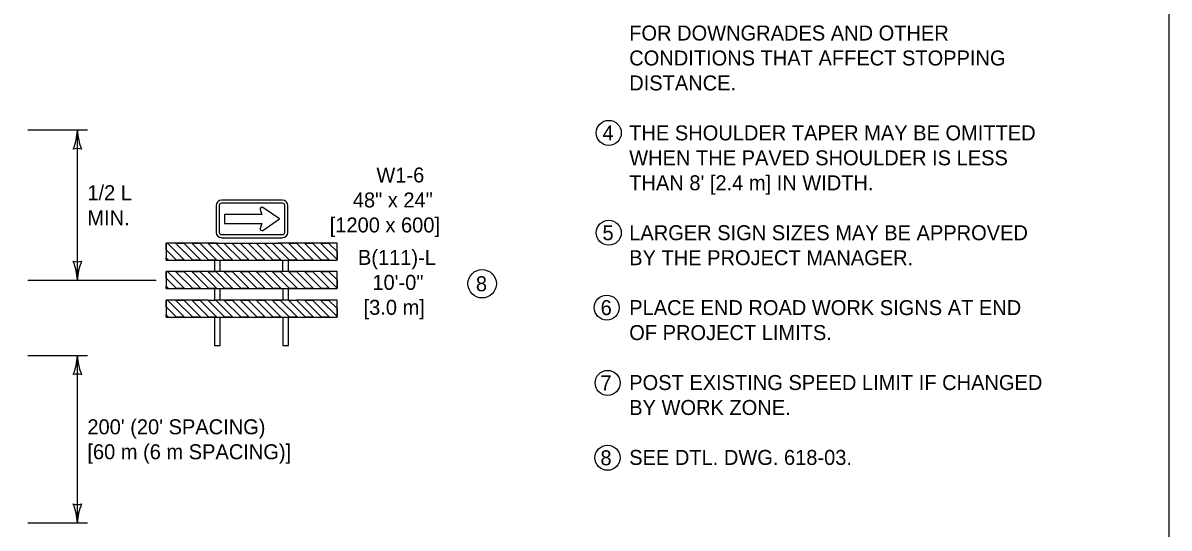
# Model space of a CAD drawing. Extents: x 49991.4 to 50021, y 49987.6 to 50011.4.
# Drawn here: x 50004.026 to 50008.615, y 50006.247 to 50008.271 of the extents above; entities that cross this region are included whole.
import ezdxf

# ---------------------------------------------------------------- set-up
doc = ezdxf.new("R2010")
doc.units = 0
for name, color, linetype in [('Level 1', 7, 'Continuous'), ('Level 2', 7, 'Continuous'), ('Level 3', 7, 'Continuous')]:
    doc.layers.add(name, color=color, linetype=linetype)

msp = doc.modelspace()

# ---------------------------------------------------------------- linework, layer by layer
at = {"layer": 'Level 1'}
for p, q in [((50004.7996, 50007.5398), (50004.7996, 50007.4315)), ((50004.812, 50007.5398), (50004.812, 50007.4315)), ((50005.0657, 50007.5607), (50004.8206, 50007.5607)), ((50005.0657, 50007.5483), (50004.8206, 50007.5483)), ((50005.0742, 50007.4315), (50005.0742, 50007.5398)), ((50005.0866, 50007.4315), (50005.0866, 50007.5398)), ((50004.9718, 50007.5039), (50004.8336, 50007.5039)), ((50004.8336, 50007.5039), (50004.8336, 50007.4674)), ((50004.982, 50007.5039), (50004.9718, 50007.5039)), ((50004.9756, 50007.5234), (50004.982, 50007.5039)), ((50005.0526, 50007.4856), (50004.9862, 50007.5313)), ((50004.8336, 50007.4674), (50004.982, 50007.4674)), ((50004.982, 50007.4674), (50004.9756, 50007.4478)), ((50004.9862, 50007.4399), (50005.0526, 50007.4856)), ((50004.8206, 50007.4229), (50005.0657, 50007.4229)), ((50004.8206, 50007.4105), (50005.0657, 50007.4105)), ((50004.6413, 50007.3203), (50004.5996, 50007.3621)), ((50004.6413, 50007.3203), (50004.5996, 50007.3621)), ((50004.6735, 50007.3203), (50004.6051, 50007.3887)), ((50004.6051, 50007.3887), (50004.6735, 50007.3203)), ((50004.7058, 50007.3203), (50004.6374, 50007.3887)), ((50004.7058, 50007.3203), (50004.6374, 50007.3887)), ((50004.7381, 50007.3203), (50004.6697, 50007.3887)), ((50004.6697, 50007.3887), (50004.7381, 50007.3203)), ((50004.7703, 50007.3203), (50004.7019, 50007.3887)), ((50004.7703, 50007.3203), (50004.7019, 50007.3887)), ((50004.8025, 50007.3203), (50004.7341, 50007.3887)), ((50004.7341, 50007.3887), (50004.8025, 50007.3203)), ((50004.8348, 50007.3203), (50004.7664, 50007.3887)), ((50004.867, 50007.3203), (50004.7986, 50007.3887)), ((50004.7986, 50007.3887), (50004.8385, 50007.3887)), ((50004.819, 50007.3887), (50005.0641, 50007.3887)), ((50004.8992, 50007.3203), (50004.8308, 50007.3887)), ((50004.9314, 50007.3203), (50004.863, 50007.3887)), ((50004.9636, 50007.3203), (50004.8952, 50007.3887)), ((50004.9958, 50007.3203), (50004.9274, 50007.3887)), ((50005.028, 50007.3203), (50004.9596, 50007.3887)), ((50005.0602, 50007.3203), (50004.9918, 50007.3887)), ((50005.0927, 50007.3203), (50005.0243, 50007.3887)), ((50005.0784, 50007.3887), (50005.047, 50007.3887)), ((50005.1249, 50007.3203), (50005.0565, 50007.3887)), ((50005.1572, 50007.3203), (50005.0888, 50007.3887)), ((50005.1572, 50007.3203), (50005.0888, 50007.3887)), ((50005.1894, 50007.3203), (50005.121, 50007.3887)), ((50005.121, 50007.3887), (50005.1894, 50007.3203)), ((50005.2217, 50007.3203), (50005.1533, 50007.3887)), ((50005.2217, 50007.3203), (50005.1533, 50007.3887)), ((50005.2539, 50007.3203), (50005.1855, 50007.3887)), ((50005.1855, 50007.3887), (50005.2539, 50007.3203)), ((50005.2836, 50007.3229), (50005.2177, 50007.3887)), ((50005.2836, 50007.3229), (50005.2177, 50007.3887)), ((50005.2836, 50007.3551), (50005.25, 50007.3887)), ((50005.25, 50007.3887), (50005.2836, 50007.3551)), ((50004.6091, 50007.3203), (50004.5996, 50007.3298)), ((50004.5996, 50007.3298), (50004.6091, 50007.3203)), ((50004.8162, 50007.2748), (50004.8162, 50007.3203)), ((50005.067, 50007.2748), (50005.067, 50007.3203)), ((50004.6735, 50007.2064), (50004.6051, 50007.2748)), ((50004.6051, 50007.2748), (50004.6735, 50007.2064)), ((50004.7058, 50007.2064), (50004.6374, 50007.2748)), ((50004.7058, 50007.2064), (50004.6374, 50007.2748)), ((50004.7381, 50007.2064), (50004.6697, 50007.2748)), ((50004.6697, 50007.2748), (50004.7381, 50007.2064)), ((50004.7703, 50007.2064), (50004.7019, 50007.2748)), ((50004.7703, 50007.2064), (50004.7019, 50007.2748)), ((50004.8025, 50007.2064), (50004.7341, 50007.2748)), ((50004.7341, 50007.2748), (50004.8025, 50007.2064)), ((50004.8048, 50007.2364), (50004.7664, 50007.2748)), ((50004.8048, 50007.2686), (50004.7986, 50007.2748)), ((50004.867, 50007.2064), (50004.8048, 50007.2686)), ((50004.8993, 50007.2064), (50004.8309, 50007.2748)), ((50004.9315, 50007.2064), (50004.8631, 50007.2748)), ((50004.9637, 50007.2064), (50004.8953, 50007.2748)), ((50004.996, 50007.2064), (50004.9276, 50007.2748)), ((50005.0282, 50007.2064), (50004.9598, 50007.2748)), ((50005.0605, 50007.2064), (50004.9921, 50007.2748)), ((50005.0927, 50007.2064), (50005.0243, 50007.2748)), ((50005.1249, 50007.2064), (50005.0565, 50007.2748)), ((50005.1572, 50007.2064), (50005.0888, 50007.2748)), ((50005.1572, 50007.2064), (50005.0888, 50007.2748)), ((50005.1894, 50007.2064), (50005.121, 50007.2748)), ((50005.121, 50007.2748), (50005.1894, 50007.2064)), ((50005.2217, 50007.2064), (50005.1533, 50007.2748)), ((50005.2217, 50007.2064), (50005.1533, 50007.2748)), ((50005.2539, 50007.2064), (50005.1855, 50007.2748)), ((50005.1855, 50007.2748), (50005.2539, 50007.2064)), ((50005.2836, 50007.2089), (50005.2177, 50007.2748)), ((50005.2836, 50007.2089), (50005.2177, 50007.2748)), ((50005.2836, 50007.2411), (50005.25, 50007.2748)), ((50005.25, 50007.2748), (50005.2836, 50007.2411)), ((50004.6413, 50007.2064), (50004.5996, 50007.2481)), ((50004.6413, 50007.2064), (50004.5996, 50007.2481)), ((50004.8348, 50007.2064), (50004.8048, 50007.2364)), ((50004.6091, 50007.2064), (50004.5996, 50007.2159)), ((50004.5996, 50007.2159), (50004.6091, 50007.2064)), ((50004.6413, 50007.0924), (50004.5996, 50007.1341)), ((50004.6413, 50007.0924), (50004.5996, 50007.1341)), ((50004.6735, 50007.0924), (50004.6051, 50007.1608)), ((50004.6051, 50007.1608), (50004.6735, 50007.0924)), ((50004.7058, 50007.0924), (50004.6374, 50007.1608)), ((50004.7058, 50007.0924), (50004.6374, 50007.1608)), ((50004.7381, 50007.0924), (50004.6697, 50007.1608)), ((50004.6697, 50007.1608), (50004.7381, 50007.0924)), ((50004.7703, 50007.0924), (50004.7019, 50007.1608)), ((50004.7703, 50007.0924), (50004.7019, 50007.1608)), ((50004.8025, 50007.0924), (50004.7341, 50007.1608)), ((50004.7341, 50007.1608), (50004.8025, 50007.0924)), ((50004.8348, 50007.0924), (50004.7664, 50007.1608)), ((50004.8348, 50007.0924), (50004.7664, 50007.1608)), ((50004.867, 50007.0924), (50004.7986, 50007.1608)), ((50004.7986, 50007.1608), (50004.867, 50007.0924)), ((50004.8993, 50007.0924), (50004.8309, 50007.1608)), ((50004.8993, 50007.0924), (50004.8309, 50007.1608)), ((50004.9315, 50007.0924), (50004.8631, 50007.1608)), ((50004.8631, 50007.1608), (50004.9315, 50007.0924)), ((50004.9637, 50007.0924), (50004.8953, 50007.1608)), ((50004.9637, 50007.0924), (50004.8953, 50007.1608)), ((50004.996, 50007.0924), (50004.9276, 50007.1608)), ((50004.9276, 50007.1608), (50004.996, 50007.0924)), ((50005.0282, 50007.0924), (50004.9598, 50007.1608)), ((50005.0282, 50007.0924), (50004.9598, 50007.1608)), ((50005.0605, 50007.0924), (50004.9921, 50007.1608)), ((50004.9921, 50007.1608), (50005.0605, 50007.0924)), ((50005.0927, 50007.0924), (50005.0243, 50007.1608)), ((50005.0927, 50007.0924), (50005.0243, 50007.1608)), ((50005.1249, 50007.0924), (50005.0565, 50007.1608)), ((50005.0565, 50007.1608), (50005.1249, 50007.0924)), ((50005.1572, 50007.0924), (50005.0888, 50007.1608)), ((50005.1572, 50007.0924), (50005.0888, 50007.1608)), ((50005.1894, 50007.0924), (50005.121, 50007.1608)), ((50005.121, 50007.1608), (50005.1894, 50007.0924)), ((50005.2217, 50007.0924), (50005.1533, 50007.1608)), ((50005.2217, 50007.0924), (50005.1533, 50007.1608)), ((50005.2539, 50007.0924), (50005.1855, 50007.1608)), ((50005.1855, 50007.1608), (50005.2539, 50007.0924)), ((50005.2836, 50007.0949), (50005.2177, 50007.1608)), ((50005.2836, 50007.0949), (50005.2177, 50007.1608)), ((50005.2836, 50007.1272), (50005.25, 50007.1608)), ((50005.25, 50007.1608), (50005.2836, 50007.1272)), ((50004.6091, 50007.0924), (50004.5996, 50007.1019)), ((50004.5996, 50007.1019), (50004.6091, 50007.0924))]:
    msp.add_line(p, q, dxfattribs=at)
msp.add_lwpolyline([(50008.6146, 50011.2628), (50000.3356, 50011.2628), (50000.3356, 50000.0624), (50008.6146, 50000.0624)], close=True, dxfattribs=at)
for points in [[(50004.8048, 50007.3887), (50004.5996, 50007.3887), (50004.5996, 50007.3203), (50004.8048, 50007.3203)], [(50004.5996, 50007.3621), (50004.5996, 50007.3887), (50004.6051, 50007.3887)], [(50004.6374, 50007.3887), (50004.6697, 50007.3887)], [(50004.7019, 50007.3887), (50004.7341, 50007.3887)], [(50004.867, 50007.3203), (50004.8348, 50007.3203), (50004.7664, 50007.3887), (50004.7986, 50007.3887), (50004.867, 50007.3203)], [(50004.8048, 50007.3203), (50005.2836, 50007.3203), (50005.2836, 50007.3887), (50005.0784, 50007.3887)], [(50004.8308, 50007.3887), (50004.8385, 50007.3887), (50004.863, 50007.3887), (50004.9314, 50007.3203), (50004.8992, 50007.3203), (50004.8308, 50007.3887)], [(50004.8952, 50007.3887), (50004.9274, 50007.3887), (50004.9958, 50007.3203), (50004.9636, 50007.3203), (50004.8952, 50007.3887)], [(50004.9596, 50007.3887), (50004.9918, 50007.3887), (50005.0602, 50007.3203), (50005.028, 50007.3203), (50004.9596, 50007.3887)], [(50005.0243, 50007.3887), (50005.047, 50007.3887), (50005.0565, 50007.3887), (50005.1249, 50007.3203), (50005.0927, 50007.3203), (50005.0243, 50007.3887)], [(50005.0888, 50007.3887), (50005.121, 50007.3887)], [(50005.1533, 50007.3887), (50005.1855, 50007.3887)], [(50005.2177, 50007.3887), (50005.25, 50007.3887)], [(50005.2836, 50007.3551), (50005.2836, 50007.3229)], [(50004.6091, 50007.3203), (50004.5996, 50007.3203), (50004.5996, 50007.3298)], [(50004.6735, 50007.3203), (50004.6413, 50007.3203)], [(50004.7381, 50007.3203), (50004.7058, 50007.3203)], [(50004.8025, 50007.3203), (50004.7703, 50007.3203)], [(50004.7934, 50007.3203), (50004.7934, 50007.2748)], [(50005.0898, 50007.2747), (50005.0898, 50007.3203)], [(50005.1894, 50007.3203), (50005.1572, 50007.3203)], [(50005.2539, 50007.3203), (50005.2217, 50007.3203)], [(50004.8048, 50007.2748), (50004.5996, 50007.2748), (50004.5996, 50007.2064), (50005.2836, 50007.2064), (50005.2836, 50007.2748), (50004.8048, 50007.2748)], [(50004.5996, 50007.2481), (50004.5996, 50007.2748), (50004.6051, 50007.2748)], [(50004.6374, 50007.2748), (50004.6697, 50007.2748)], [(50004.7019, 50007.2748), (50004.7341, 50007.2748)], [(50004.867, 50007.2064), (50004.8348, 50007.2064), (50004.8048, 50007.2364), (50004.7664, 50007.2748), (50004.7934, 50007.2748), (50004.7986, 50007.2748), (50004.8048, 50007.2686), (50004.867, 50007.2064)], [(50004.8309, 50007.2748), (50004.8631, 50007.2748), (50004.9315, 50007.2064), (50004.8993, 50007.2064), (50004.8309, 50007.2748)], [(50004.8953, 50007.2748), (50004.9276, 50007.2748), (50004.996, 50007.2064), (50004.9637, 50007.2064), (50004.8953, 50007.2748)], [(50004.9598, 50007.2748), (50004.9921, 50007.2748), (50005.0605, 50007.2064), (50005.0282, 50007.2064), (50004.9598, 50007.2748)], [(50005.0243, 50007.2748), (50005.0565, 50007.2748), (50005.1249, 50007.2064), (50005.0927, 50007.2064), (50005.0243, 50007.2748)], [(50005.0888, 50007.2748), (50005.121, 50007.2748)], [(50005.1533, 50007.2748), (50005.1855, 50007.2748)], [(50005.2177, 50007.2748), (50005.25, 50007.2748)], [(50005.2836, 50007.2411), (50005.2836, 50007.2089)], [(50004.6091, 50007.2064), (50004.5996, 50007.2064), (50004.5996, 50007.2159)], [(50004.6735, 50007.2064), (50004.6413, 50007.2064)], [(50004.7381, 50007.2064), (50004.7058, 50007.2064)], [(50004.8025, 50007.2064), (50004.7703, 50007.2064)], [(50004.7934, 50007.2064), (50004.7934, 50007.1608)], [(50004.8162, 50007.1608), (50004.8162, 50007.2064)], [(50005.067, 50007.2064), (50005.067, 50007.1608)], [(50005.0898, 50007.1608), (50005.0898, 50007.2064)], [(50005.1894, 50007.2064), (50005.1572, 50007.2064)], [(50005.2539, 50007.2064), (50005.2217, 50007.2064)], [(50004.5996, 50007.1341), (50004.5996, 50007.1608), (50004.6051, 50007.1608)], [(50004.7664, 50007.1608), (50004.5996, 50007.1608), (50004.5996, 50007.0924), (50005.2836, 50007.0924), (50005.2836, 50007.1608), (50005.121, 50007.1608)], [(50004.6374, 50007.1608), (50004.6697, 50007.1608)], [(50004.7019, 50007.1608), (50004.7341, 50007.1608)], [(50004.7664, 50007.1608), (50004.7986, 50007.1608)], [(50005.0888, 50007.1608), (50004.7986, 50007.1608)], [(50004.8309, 50007.1608), (50004.8631, 50007.1608)], [(50004.8953, 50007.1608), (50004.9276, 50007.1608)], [(50004.9598, 50007.1608), (50004.9921, 50007.1608)], [(50005.0243, 50007.1608), (50005.0565, 50007.1608)], [(50005.0888, 50007.1608), (50005.121, 50007.1608)], [(50005.1533, 50007.1608), (50005.1855, 50007.1608)], [(50005.2177, 50007.1608), (50005.25, 50007.1608)], [(50005.2836, 50007.1272), (50005.2836, 50007.0949)], [(50004.6091, 50007.0924), (50004.5996, 50007.0924), (50004.5996, 50007.1019)], [(50004.6735, 50007.0924), (50004.6413, 50007.0924)], [(50004.7381, 50007.0924), (50004.7058, 50007.0924)], [(50004.8025, 50007.0924), (50004.7703, 50007.0924)], [(50004.7934, 50007.0923), (50004.7934, 50006.9783), (50004.8162, 50006.9783), (50004.8162, 50007.0923)], [(50004.867, 50007.0924), (50004.8348, 50007.0924)], [(50004.9315, 50007.0924), (50004.8993, 50007.0924)], [(50004.996, 50007.0924), (50004.9637, 50007.0924)], [(50005.0605, 50007.0924), (50005.0282, 50007.0924)], [(50005.067, 50007.0923), (50005.067, 50006.9783), (50005.0898, 50006.9783), (50005.0898, 50007.0923)], [(50005.1249, 50007.0924), (50005.0927, 50007.0924)], [(50005.1894, 50007.0924), (50005.1572, 50007.0924)], [(50005.2539, 50007.0924), (50005.2217, 50007.0924)]]:
    msp.add_lwpolyline(points, dxfattribs=at)
for centre, radius, start, end in [((50004.8206, 50007.5398), 0.0209, 90, 180), ((50004.8206, 50007.5398), 0.00855, 90, 180), ((50005.0657, 50007.5398), 0.0209, 0, 90), ((50005.0657, 50007.5398), 0.00855, 0, 90), ((50004.9822, 50007.5256), 0.00695, 55.4806, 197.9582), ((50004.9822, 50007.4456), 0.00695, 162.0418, 304.5194), ((50004.8206, 50007.4315), 0.0209, 180, 270), ((50004.8206, 50007.4315), 0.00855, 180, 270), ((50005.0657, 50007.4315), 0.00855, 270, 360), ((50005.0657, 50007.4315), 0.0209, 270, 360)]:
    msp.add_arc(centre, radius, start, end, dxfattribs=at)
at = {"layer": 'Level 2'}
for centre, radius in [((50006.3715, 50007.8304), 0.0501), ((50006.3715, 50007.4304), 0.0501), ((50005.8644, 50007.2259), 0.0569), ((50006.3632, 50007.1303), 0.0501), ((50006.3668, 50006.8289), 0.0501), ((50006.3663, 50006.5289), 0.0501)]:
    msp.add_circle(centre, radius, dxfattribs=at)
at = {"layer": 'Level 3'}
for p, q in [((50004.284, 50007.8406), (50004.046, 50007.8406)), ((50004.244, 50007.2406), (50004.244, 50007.8406)), ((50004.046, 50007.2406), (50004.5596, 50007.2406)), ((50004.046, 50006.9379), (50004.284, 50006.9379)), ((50004.244, 50006.2679), (50004.244, 50006.9379)), ((50004.046, 50006.2679), (50004.284, 50006.2679))]:
    msp.add_line(p, q, dxfattribs=at)
for centre, radius, start, end in [((50004.0219, 50007.8497), 0.2223, 337.456, 357.6395), ((50004.4767, 50007.8521), 0.233, 182.8273, 202.0772), ((50004.244, 50007.7123), 0.0548, 72.1388, 107.8612), ((50004.244, 50007.3688), 0.0548, 252.1388, 287.8612), ((50004.0113, 50007.2291), 0.233, 2.8273, 22.0772), ((50004.4661, 50007.2314), 0.2223, 157.456, 177.6395), ((50004.0219, 50006.947), 0.2223, 337.456, 357.6395), ((50004.4767, 50006.9493), 0.233, 182.8273, 202.0772), ((50004.244, 50006.8096), 0.0548, 72.1388, 107.8612), ((50004.244, 50006.3961), 0.0548, 252.1388, 287.8612), ((50004.0113, 50006.2564), 0.233, 2.8273, 22.0772), ((50004.4661, 50006.2587), 0.2223, 157.456, 177.6395)]:
    msp.add_arc(centre, radius, start, end, dxfattribs=at)

# ---------------------------------------------------------------- texts
at = {"layer": 'Level 2'}
for s, p in [('FOR DOWNGRADES AND OTHER ', (50006.4533, 50008.2003)), ('CONDITIONS THAT AFFECT STOPPING ', (50006.4533, 50008.1003)), ('DISTANCE. ', (50006.4533, 50008.0003)), ('4', (50006.3462, 50007.8003)), ('THE SHOULDER TAPER MAY BE OMITTED ', (50006.4533, 50007.8003)), ('WHEN THE PAVED SHOULDER IS LESS ', (50006.4533, 50007.7003)), ('W1-6', (50005.4411, 50007.6315)), ("THAN 8' [2.4 m] IN WIDTH.", (50006.4533, 50007.6003)), ('1/2 L ', (50004.284, 50007.5606)), ('48" x 24"', (50005.3467, 50007.5315)), ('MIN.', (50004.284, 50007.4606)), ('[1200 x 600]', (50005.2542, 50007.4315)), ('5', (50006.3462, 50007.4003)), ('LARGER SIGN SIZES MAY BE APPROVED ', (50006.4533, 50007.4003)), ('B(111)-L', (50005.3673, 50007.3015)), ('BY THE PROJECT MANAGER.', (50006.4533, 50007.3003)), ('10\'-0"', (50005.4251, 50007.2015)), ('8', (50005.8394, 50007.1959)), ('[3.0 m]', (50005.3898, 50007.1015)), ('6', (50006.3388, 50007.1004)), ('PLACE END ROAD WORK SIGNS AT END ', (50006.4533, 50007.1003)), ('OF PROJECT LIMITS.', (50006.4533, 50007.0003)), ('7', (50006.3381, 50006.7988)), ('POST EXISTING SPEED LIMIT IF CHANGED ', (50006.4533, 50006.8003)), ('BY WORK ZONE.', (50006.4533, 50006.7003)), ("200' (20' SPACING)", (50004.284, 50006.6229)), ('[60 m (6 m SPACING)]', (50004.284, 50006.5229)), ('8', (50006.3381, 50006.4988)), ('SEE DTL. DWG. 618-03.', (50006.4533, 50006.5003))]:
    msp.add_text(s, height=0.06, dxfattribs=at).set_placement(p)

doc.saveas('drawing.dxf')
